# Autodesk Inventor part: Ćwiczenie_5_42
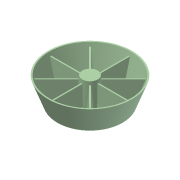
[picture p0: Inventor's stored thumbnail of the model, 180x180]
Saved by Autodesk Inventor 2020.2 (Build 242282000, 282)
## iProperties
Created: 2006-08
Part Number: Ćwiczenie_5_42
Document SubType Name: Modeling
Designer: F.Stasiak
Density: 1 g/cm^3
Material: Ogólny
Appearance: Zielony pastelowy
Manager: www.cadconsulting.pl
Company: Fabian Stasiak CAD Consulting
Author: F.Stasiak
Subject: Zbiór ćwiczeń. Autodesk Inventor 2020. Kurs podstawowy
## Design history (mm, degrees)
sketch "Szkic1"
  geometry: C1 r 50 at (0, 0); 1 further point
  constraints: 1 centre point, 1 coincident
  dimensions: "d0" = 100 diameter of C1
extrude "Wyciągnięcie proste1" new body sketch "Szkic1" distance "d1" = 40; taper "d2" = 20 deg
feature "Skorupa1" dims "d3" = 2, "d7" = 5
sketch "Szkic2"
  geometry: C1 r 49.691 at (0, 0) reference; C2 r 15 at (0, 0)
  constraints: 1 centre point, 1 coincident
  dimensions: "d4" = 30 diameter of C2
extrude "Wyciągnięcie proste2" join sketch "Szkic2" distance "d5" = 35; taper "d6" = -5 deg
node "Płaszczyzna konstrukcyjna1"
fillet "Zaokrąglenie1" dims "d21" = 4
sketch "Szkic3"
  geometry: L1 (0, 0)-(-64.559, 0); L2 (0, 0)-(-45.65, -45.65); L3 (0, 0)-(0, -64.559); L4 (0, 0)-(45.65, -45.65); L5 (0, 0)-(64.559, 0); L6 (0, 0)-(45.65, 45.65); L7 (0, 0)-(0, 64.559); L8 (0, 0)-(-45.65, 45.65); 1 further point
  constraints: 16 end point, 8 coincident, 8 equal length, 1 horizontal, 1 horizontal alignment, 9 other
  dimensions: "d11" = 360 deg dimension on L1.start L1.end (derived)
feature "Żebro1" sketch "Szkic3" dims "d13" = 2, "d14" = 1, "d15" = 5 deg
sketch "Szkic4"
  geometry: L1 (-30, 12.5)-(30, 12.5); L2 (30, 12.5)-(30, -12.5); L3 (30, -12.5)-(-30, -12.5); L4 (-30, -12.5)-(-30, 12.5); L5 (0, 12.5)-(0, -12.5); L6 (-12, 0)-(-12, 15.823); L7 (12, 15.823)-(12, -15.823); L8 (-12, -15.823)-(-12, 0); L9 (0, 12.5)-(0, -12.5); L10 (0, 15.823)-(0, -15.823); A1 r 12 centre (0, 15.823) between (12, 15.823) and (-12, 15.823); A2 r 12 centre (0, -15.823) between (-12, -15.823) and (12, -15.823); 3 further points
  constraints: 20 end point, 5 midpoint, 4 perpendicular, 4 point on circle, 4 tangent, 3 parallel, 2 centre point, 1 coincident, 1 collinear, 1 horizontal
  dimensions: "d16" = 60 distance of L2.end L3.end; "d17" = 25 distance of L1.end L2.end; "d18" = 12 radius of A1
extrude "Wyciągnięcie proste3" cut sketch "Szkic4" distance "d19" = 3; taper "d20" = 0 deg
node "Bryła1"
node "Korpusy bryłowe"
node "Korpusy powierzchniowe"
other parameters: "d8" = -5
